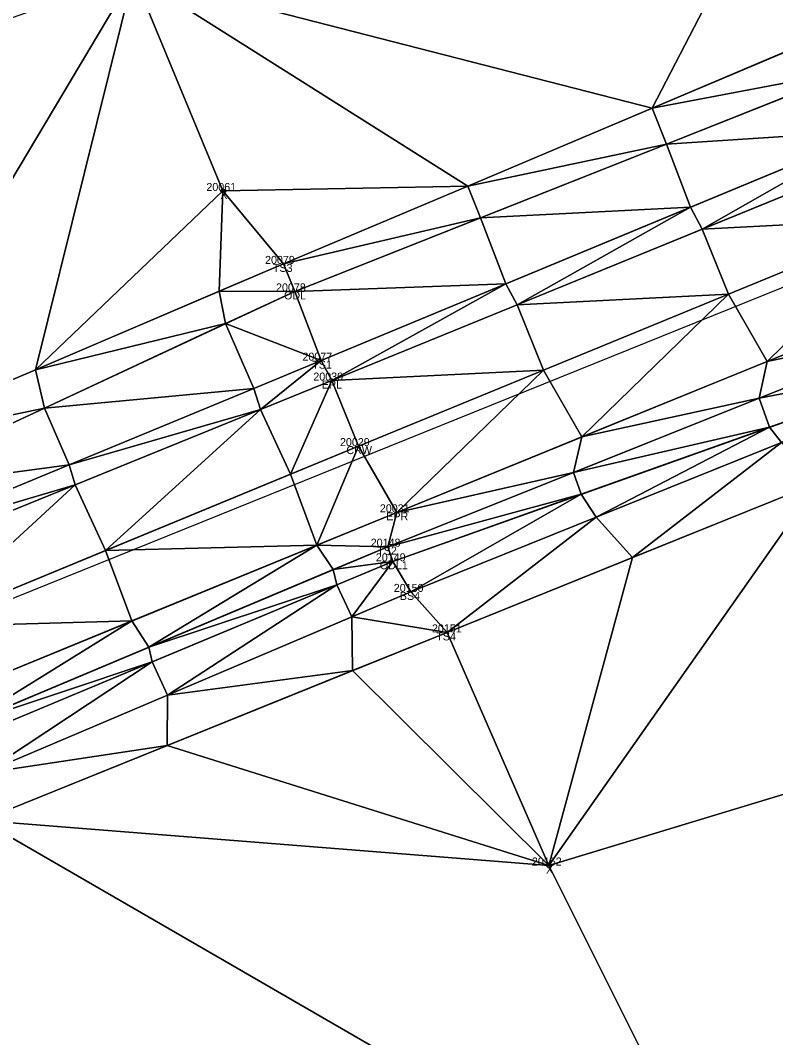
# Model space of a CAD drawing. Extents: x 1966740 to 1969291, y 1117379 to 1118460.
# Drawn here: x 1967133.7 to 1967228, y 1117539.4 to 1117666.5 of the extents above; entities that cross this region are included whole.
import ezdxf

# ---------------------------------------------------------------- set-up
doc = ezdxf.new("R2010")
doc.units = 0
for name, color, linetype in [('Level 1', 7, 'Continuous'), ('Level 3', 7, 'Continuous'), ('Level 30', 7, 'Continuous'), ('Level 35', 7, 'Continuous'), ('Level 50', 7, 'Continuous'), ('Level 52', 7, 'Continuous'), ('Level 53', 7, 'Continuous'), ('Level 56', 7, 'Continuous'), ('Level 6', 7, 'Continuous'), ('Level 62', 7, 'Continuous')]:
    doc.layers.add(name, color=color, linetype=linetype)

msp = doc.modelspace()

# ---------------------------------------------------------------- linework, layer by layer
at = {"layer": 'Level 1'}
msp.add_line((1966770.74, 1117448.12), (1967849.47, 1117883.86), dxfattribs=at)
at = {"layer": 'Level 3'}
for points in [[(1966768.15, 1117461.43), (1966869.41, 1117499.34), (1967070.52, 1117582.35), (1967171.25, 1117624.02), (1967269.74, 1117664.9), (1967320.21, 1117685.71), (1967369.37, 1117708.48), (1967468.51, 1117746.66), (1967564.6, 1117784.47), (1967654.68, 1117828.05), (1967680.1, 1117841.48), (1967687.91, 1117842.93), (1967691.45, 1117838.71), (1967693.03, 1117834.22)], [(1966769.51, 1117457.48), (1966870.16, 1117497.34), (1966971.19, 1117538.95), (1967071.09, 1117580.24), (1967172.6, 1117621.53), (1967270.79, 1117661.66), (1967321.12, 1117682.57), (1967371.52, 1117702.88), (1967470.26, 1117741.55), (1967566.67, 1117779.5), (1967661.25, 1117817.53), (1967694.4, 1117831.19), (1967697.89, 1117822.8)], [(1966772.57, 1117449.88), (1966874.49, 1117489.87), (1966974.64, 1117529.93), (1967075.06, 1117571.68), (1967175.91, 1117613.34), (1967274.11, 1117653.69), (1967325.25, 1117674.8), (1967374.73, 1117695.01), (1967473.9, 1117733.1), (1967569.8, 1117771.9), (1967665.19, 1117809.79), (1967697.89, 1117822.8)], [(1966766.42, 1117472.19), (1966865.47, 1117508.82), (1967066.64, 1117593.45), (1967166.55, 1117636.11), (1967264.62, 1117677.56), (1967315.66, 1117698.57), (1967367.9, 1117716.34), (1967464.92, 1117753.87), (1967560.73, 1117793.63)], [(1966775.75, 1117440.57), (1966876.18, 1117480.39), (1966978.46, 1117522.15), (1967078.26, 1117563.06), (1967180.7, 1117605.06), (1967277.98, 1117644.72), (1967308.82, 1117656.67)], [(1967048.76, 1117544.94), (1967049.4, 1117546.86), (1967080.66, 1117559.16), (1967179.58, 1117600.77), (1967277.28, 1117639.86), (1967309.81, 1117650.85), (1967314.11, 1117648.69)], [(1967048.76, 1117544.94), (1967051.21, 1117542.08), (1967082.51, 1117547.84), (1967186.99, 1117590.06), (1967282.24, 1117628.54), (1967312.54, 1117644.56), (1967314.11, 1117648.69)], [(1967057.9, 1117544.76), (1967083.08, 1117552.93), (1967182.44, 1117595.12), (1967280.35, 1117634.58)]]:
    msp.add_lwpolyline(points, dxfattribs=at)
at = {"layer": 'Level 30'}
for centre in [(1967158.99, 1117645.22), (1967199.69, 1117560.93)]:
    msp.add_circle(centre, 0.25, dxfattribs=at)
at = {"layer": 'Level 35'}
for points in [[(1967147.82, 1117672.22), (1967244.6, 1117717.31), (1967212.59, 1117655.57)], [(1967212.59, 1117655.57), (1967244.6, 1117717.31), (1967235.6, 1117665.3)], [(1967045.28, 1117636.33), (1967147.82, 1117672.22), (1967112.59, 1117613.07)], [(1967112.59, 1117613.07), (1967147.82, 1117672.22), (1967135.56, 1117622.88)], [(1967135.56, 1117622.88), (1967147.82, 1117672.22), (1967158.99, 1117645.22)], [(1967147.82, 1117672.22), (1967212.59, 1117655.57), (1967189.57, 1117645.84)], [(1967147.82, 1117672.22), (1967189.57, 1117645.84), (1967158.99, 1117645.22)], [(1967212.59, 1117655.57), (1967235.6, 1117665.3), (1967237.63, 1117660.3)], [(1967212.59, 1117655.57), (1967237.63, 1117660.3), (1967214.4, 1117651.09)], [(1967214.4, 1117651.09), (1967237.63, 1117660.3), (1967240.49, 1117652.76)], [(1967189.57, 1117645.84), (1967212.59, 1117655.57), (1967214.4, 1117651.09)], [(1967214.4, 1117651.09), (1967240.49, 1117652.76), (1967217.41, 1117643.18)], [(1967217.41, 1117643.18), (1967240.49, 1117652.76), (1967218.86, 1117640.44)], [(1967218.86, 1117640.44), (1967240.49, 1117652.76), (1967241.99, 1117649.89)], [(1967189.57, 1117645.84), (1967214.4, 1117651.09), (1967191.17, 1117641.88)], [(1967191.17, 1117641.88), (1967214.4, 1117651.09), (1967217.41, 1117643.18)], [(1967218.86, 1117640.44), (1967241.99, 1117649.89), (1967245.24, 1117641.83)], [(1967158.99, 1117645.22), (1967189.57, 1117645.84), (1967166.55, 1117636.11)], [(1967166.55, 1117636.11), (1967189.57, 1117645.84), (1967191.17, 1117641.88)], [(1967135.56, 1117622.88), (1967158.99, 1117645.22), (1967158.53, 1117632.69)], [(1967158.53, 1117632.69), (1967158.99, 1117645.22), (1967166.55, 1117636.11)], [(1967191.17, 1117641.88), (1967217.41, 1117643.18), (1967194.33, 1117633.6)], [(1967194.33, 1117633.6), (1967217.41, 1117643.18), (1967195.73, 1117630.98)], [(1967195.73, 1117630.98), (1967217.41, 1117643.18), (1967218.86, 1117640.44)], [(1967166.55, 1117636.11), (1967191.17, 1117641.88), (1967167.95, 1117632.67)], [(1967167.95, 1117632.67), (1967191.17, 1117641.88), (1967194.33, 1117633.6)], [(1967218.86, 1117640.44), (1967245.24, 1117641.83), (1967222.13, 1117632.33)], [(1967222.13, 1117632.33), (1967245.24, 1117641.83), (1967226.97, 1117623.93)], [(1967226.97, 1117623.93), (1967245.24, 1117641.83), (1967250.11, 1117633.36)], [(1967195.73, 1117630.98), (1967218.86, 1117640.44), (1967222.13, 1117632.33)], [(1967158.53, 1117632.69), (1967166.55, 1117636.11), (1967167.95, 1117632.67)], [(1967167.95, 1117632.67), (1967194.33, 1117633.6), (1967171.25, 1117624.02)], [(1967171.25, 1117624.02), (1967194.33, 1117633.6), (1967172.6, 1117621.53)], [(1967172.6, 1117621.53), (1967194.33, 1117633.6), (1967195.73, 1117630.98)], [(1967226.97, 1117623.93), (1967250.11, 1117633.36), (1967249.19, 1117628.62)], [(1967135.56, 1117622.88), (1967158.53, 1117632.69), (1967159.32, 1117628.65)], [(1967158.53, 1117632.69), (1967167.95, 1117632.67), (1967159.32, 1117628.65)], [(1967159.32, 1117628.65), (1967167.95, 1117632.67), (1967171.25, 1117624.02)], [(1967195.73, 1117630.98), (1967222.13, 1117632.33), (1967199.02, 1117622.84)], [(1967199.02, 1117622.84), (1967222.13, 1117632.33), (1967203.83, 1117614.49)], [(1967203.83, 1117614.49), (1967222.13, 1117632.33), (1967226.97, 1117623.93)], [(1967172.6, 1117621.53), (1967195.73, 1117630.98), (1967199.02, 1117622.84)], [(1967135.56, 1117622.88), (1967159.32, 1117628.65), (1967136.68, 1117618.09)], [(1967136.68, 1117618.09), (1967159.32, 1117628.65), (1967162.86, 1117620.55)], [(1967159.32, 1117628.65), (1967171.25, 1117624.02), (1967162.86, 1117620.55)], [(1967225.99, 1117619.34), (1967226.97, 1117623.93), (1967249.19, 1117628.62)], [(1967225.99, 1117619.34), (1967249.19, 1117628.62), (1967250.83, 1117624.08)], [(1967162.86, 1117620.55), (1967171.25, 1117624.02), (1967163.66, 1117617.9)], [(1967163.66, 1117617.9), (1967171.25, 1117624.02), (1967172.6, 1117621.53)], [(1967203.83, 1117614.49), (1967226.97, 1117623.93), (1967225.99, 1117619.34)], [(1967225.99, 1117619.34), (1967250.83, 1117624.08), (1967227.28, 1117615.7)], [(1967227.28, 1117615.7), (1967250.83, 1117624.08), (1967228.78, 1117613.8)], [(1967112.59, 1117613.07), (1967135.56, 1117622.88), (1967136.68, 1117618.09)], [(1967172.6, 1117621.53), (1967199.02, 1117622.84), (1967175.91, 1117613.34)], [(1967175.91, 1117613.34), (1967199.02, 1117622.84), (1967180.7, 1117605.06)], [(1967180.7, 1117605.06), (1967199.02, 1117622.84), (1967203.83, 1117614.49)], [(1967163.66, 1117617.9), (1967172.6, 1117621.53), (1967167.42, 1117609.83)], [(1967167.42, 1117609.83), (1967172.6, 1117621.53), (1967175.91, 1117613.34)], [(1967136.68, 1117618.09), (1967162.86, 1117620.55), (1967139.78, 1117611)], [(1967139.78, 1117611), (1967162.86, 1117620.55), (1967163.66, 1117617.9)], [(1967202.78, 1117610.06), (1967203.83, 1117614.49), (1967225.99, 1117619.34)], [(1967202.78, 1117610.06), (1967225.99, 1117619.34), (1967227.28, 1117615.7)], [(1967112.59, 1117613.07), (1967136.68, 1117618.09), (1967114.04, 1117607.53)], [(1967114.04, 1117607.53), (1967136.68, 1117618.09), (1967139.78, 1117611)], [(1967139.78, 1117611), (1967163.66, 1117617.9), (1967140.52, 1117608.48)], [(1967140.52, 1117608.48), (1967163.66, 1117617.9), (1967144.33, 1117600.3)], [(1967144.33, 1117600.3), (1967163.66, 1117617.9), (1967167.42, 1117609.83)], [(1967202.78, 1117610.06), (1967227.28, 1117615.7), (1967203.74, 1117607.32)], [(1967203.74, 1117607.32), (1967227.28, 1117615.7), (1967205.61, 1117604.46)], [(1967205.61, 1117604.46), (1967227.28, 1117615.7), (1967228.78, 1117613.8)], [(1967180.7, 1117605.06), (1967203.83, 1117614.49), (1967202.78, 1117610.06)], [(1967205.61, 1117604.46), (1967228.78, 1117613.8), (1967210.14, 1117599.41)], [(1967210.14, 1117599.41), (1967228.78, 1117613.8), (1967233.29, 1117608.76)], [(1967167.42, 1117609.83), (1967175.91, 1117613.34), (1967170.71, 1117600.97)], [(1967170.71, 1117600.97), (1967175.91, 1117613.34), (1967180.7, 1117605.06)], [(1967114.04, 1117607.53), (1967139.78, 1117611), (1967116.69, 1117601.45)], [(1967116.69, 1117601.45), (1967139.78, 1117611), (1967140.52, 1117608.48)], [(1967179.58, 1117600.77), (1967180.7, 1117605.06), (1967202.78, 1117610.06)], [(1967179.58, 1117600.77), (1967202.78, 1117610.06), (1967203.74, 1117607.32)], [(1967144.33, 1117600.3), (1967167.42, 1117609.83), (1967170.71, 1117600.97)], [(1967199.69, 1117560.93), (1967210.14, 1117599.41), (1967233.29, 1117608.76)], [(1967199.69, 1117560.93), (1967233.29, 1117608.76), (1967275.25, 1117583.86)], [(1967116.69, 1117601.45), (1967140.52, 1117608.48), (1967117.38, 1117599.07)], [(1967117.38, 1117599.07), (1967140.52, 1117608.48), (1967121.24, 1117590.76)], [(1967121.24, 1117590.76), (1967140.52, 1117608.48), (1967144.33, 1117600.3)], [(1967179.58, 1117600.77), (1967203.74, 1117607.32), (1967180.2, 1117598.94)], [(1967180.2, 1117598.94), (1967203.74, 1117607.32), (1967182.44, 1117595.12)], [(1967182.44, 1117595.12), (1967203.74, 1117607.32), (1967205.61, 1117604.46)], [(1967170.71, 1117600.97), (1967180.7, 1117605.06), (1967179.58, 1117600.77)], [(1967182.44, 1117595.12), (1967205.61, 1117604.46), (1967186.99, 1117590.06)], [(1967186.99, 1117590.06), (1967205.61, 1117604.46), (1967210.14, 1117599.41)], [(1967121.24, 1117590.76), (1967144.33, 1117600.3), (1967147.6, 1117591.49)], [(1967144.33, 1117600.3), (1967170.71, 1117600.97), (1967147.6, 1117591.49)], [(1967147.6, 1117591.49), (1967170.71, 1117600.97), (1967149.74, 1117588.22)], [(1967149.74, 1117588.22), (1967170.71, 1117600.97), (1967172.77, 1117597.91)], [(1967170.71, 1117600.97), (1967179.58, 1117600.77), (1967172.77, 1117597.91)], [(1967172.77, 1117597.91), (1967179.58, 1117600.77), (1967180.2, 1117598.94)], [(1967172.77, 1117597.91), (1967180.2, 1117598.94), (1967173.21, 1117596.02)], [(1967173.21, 1117596.02), (1967180.2, 1117598.94), (1967175.07, 1117591.99)], [(1967175.07, 1117591.99), (1967180.2, 1117598.94), (1967182.44, 1117595.12)], [(1967186.99, 1117590.06), (1967210.14, 1117599.41), (1967199.69, 1117560.93)], [(1967149.74, 1117588.22), (1967172.77, 1117597.91), (1967173.21, 1117596.02)], [(1967149.74, 1117588.22), (1967173.21, 1117596.02), (1967150.15, 1117586.4)], [(1967150.15, 1117586.4), (1967173.21, 1117596.02), (1967152.07, 1117582.23)], [(1967152.07, 1117582.23), (1967173.21, 1117596.02), (1967175.07, 1117591.99)], [(1967175.07, 1117591.99), (1967182.44, 1117595.12), (1967186.99, 1117590.06)], [(1967121.24, 1117590.76), (1967147.6, 1117591.49), (1967124.48, 1117582.01)], [(1967124.48, 1117582.01), (1967147.6, 1117591.49), (1967126.71, 1117578.54)], [(1967126.71, 1117578.54), (1967147.6, 1117591.49), (1967149.74, 1117588.22)], [(1967152.07, 1117582.23), (1967175.07, 1117591.99), (1967175.17, 1117585.28)], [(1967175.07, 1117591.99), (1967186.99, 1117590.06), (1967175.17, 1117585.28)], [(1967175.17, 1117585.28), (1967186.99, 1117590.06), (1967199.69, 1117560.93)], [(1967126.71, 1117578.54), (1967149.74, 1117588.22), (1967150.15, 1117586.4)], [(1967126.71, 1117578.54), (1967150.15, 1117586.4), (1967127.1, 1117576.77)], [(1967127.1, 1117576.77), (1967150.15, 1117586.4), (1967129.07, 1117572.46)], [(1967129.07, 1117572.46), (1967150.15, 1117586.4), (1967152.07, 1117582.23)], [(1967152.01, 1117575.92), (1967152.07, 1117582.23), (1967175.17, 1117585.28)], [(1967152.01, 1117575.92), (1967175.17, 1117585.28), (1967199.69, 1117560.93)], [(1967199.69, 1117560.93), (1967275.25, 1117583.86), (1967224.58, 1117511.21)], [(1967129.07, 1117572.46), (1967152.07, 1117582.23), (1967152.01, 1117575.92)], [(1967128.84, 1117566.56), (1967129.07, 1117572.46), (1967152.01, 1117575.92)], [(1967128.84, 1117566.56), (1967152.01, 1117575.92), (1967199.69, 1117560.93)], [(1967106.21, 1117466.35), (1967128.84, 1117566.56), (1967224.58, 1117511.21)], [(1967128.84, 1117566.56), (1967199.69, 1117560.93), (1967224.58, 1117511.21)]]:
    msp.add_lwpolyline(points, close=True, dxfattribs=at)
at = {"layer": 'Level 50'}
for centre in [(1967166.55, 1117636.11), (1967167.95, 1117632.67), (1967171.25, 1117624.02), (1967172.6, 1117621.53), (1967175.91, 1117613.34), (1967180.7, 1117605.06), (1967179.58, 1117600.77), (1967180.2, 1117598.94), (1967182.44, 1117595.12), (1967186.99, 1117590.06)]:
    msp.add_circle(centre, 0.001, dxfattribs=at)
at = {"layer": 'Level 6'}
for points in [[(1966766.64, 1117466.58), (1966867.24, 1117504.5), (1967068.76, 1117586.41), (1967167.95, 1117632.67), (1967266.82, 1117671.88), (1967316.79, 1117693.47), (1967368.01, 1117713.34), (1967465.67, 1117751.74), (1967560.73, 1117793.63)], [(1967050.24, 1117545.72), (1967081, 1117557.52), (1967180.2, 1117598.94), (1967280.35, 1117634.58), (1967311.17, 1117647.93)]]:
    msp.add_lwpolyline(points, dxfattribs=at)

# ---------------------------------------------------------------- texts
at = {"layer": 'Level 52'}
for s, p in [('20061', (1967156.92, 1117645.22)), ('20152', (1967197.58, 1117560.93))]:
    msp.add_text(s, height=1, dxfattribs=at).set_placement(p)
at = {"layer": 'Level 53'}
for s, p in [('20079', (1967164.25, 1117636.11)), ('TS3', (1967165.23, 1117635.11)), ('20077', (1967168.92, 1117624.02)), ('TS1', (1967170.14, 1117623.02)), ('20030', (1967170.28, 1117621.53)), ('EPL', (1967171.34, 1117620.53)), ('20029', (1967173.61, 1117613.34)), ('CRW', (1967174.41, 1117612.34)), ('20031', (1967178.59, 1117605.06)), ('EPR', (1967179.39, 1117604.06)), ('20148', (1967177.45, 1117600.77)), ('20149', (1967178.09, 1117598.94)), ('TS2', (1967178.26, 1117599.77)), ('ODL1', (1967178.59, 1117597.94)), ('20150', (1967180.33, 1117595.12)), ('BS4', (1967181.09, 1117594.12)), ('20151', (1967185.1, 1117590.06)), ('TS4', (1967185.64, 1117589.06))]:
    msp.add_text(s, height=1, dxfattribs=at).set_placement(p)
at = {"layer": 'Level 56'}
for s, p in [('20078', (1967165.62, 1117632.67)), ('ODL', (1967166.62, 1117631.67))]:
    msp.add_text(s, height=1, dxfattribs=at).set_placement(p)
at = {"layer": 'Level 62'}
for p in [(1967158.66, 1117644.22), (1967199.35, 1117559.93)]:
    msp.add_text('X', height=1, dxfattribs=at).set_placement(p)

doc.saveas('drawing.dxf')
